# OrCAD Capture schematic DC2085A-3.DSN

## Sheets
1 PAGE1: size Custom; title: ADAPTOR BOARD; rev: 3; note: FAST TRACK 143A
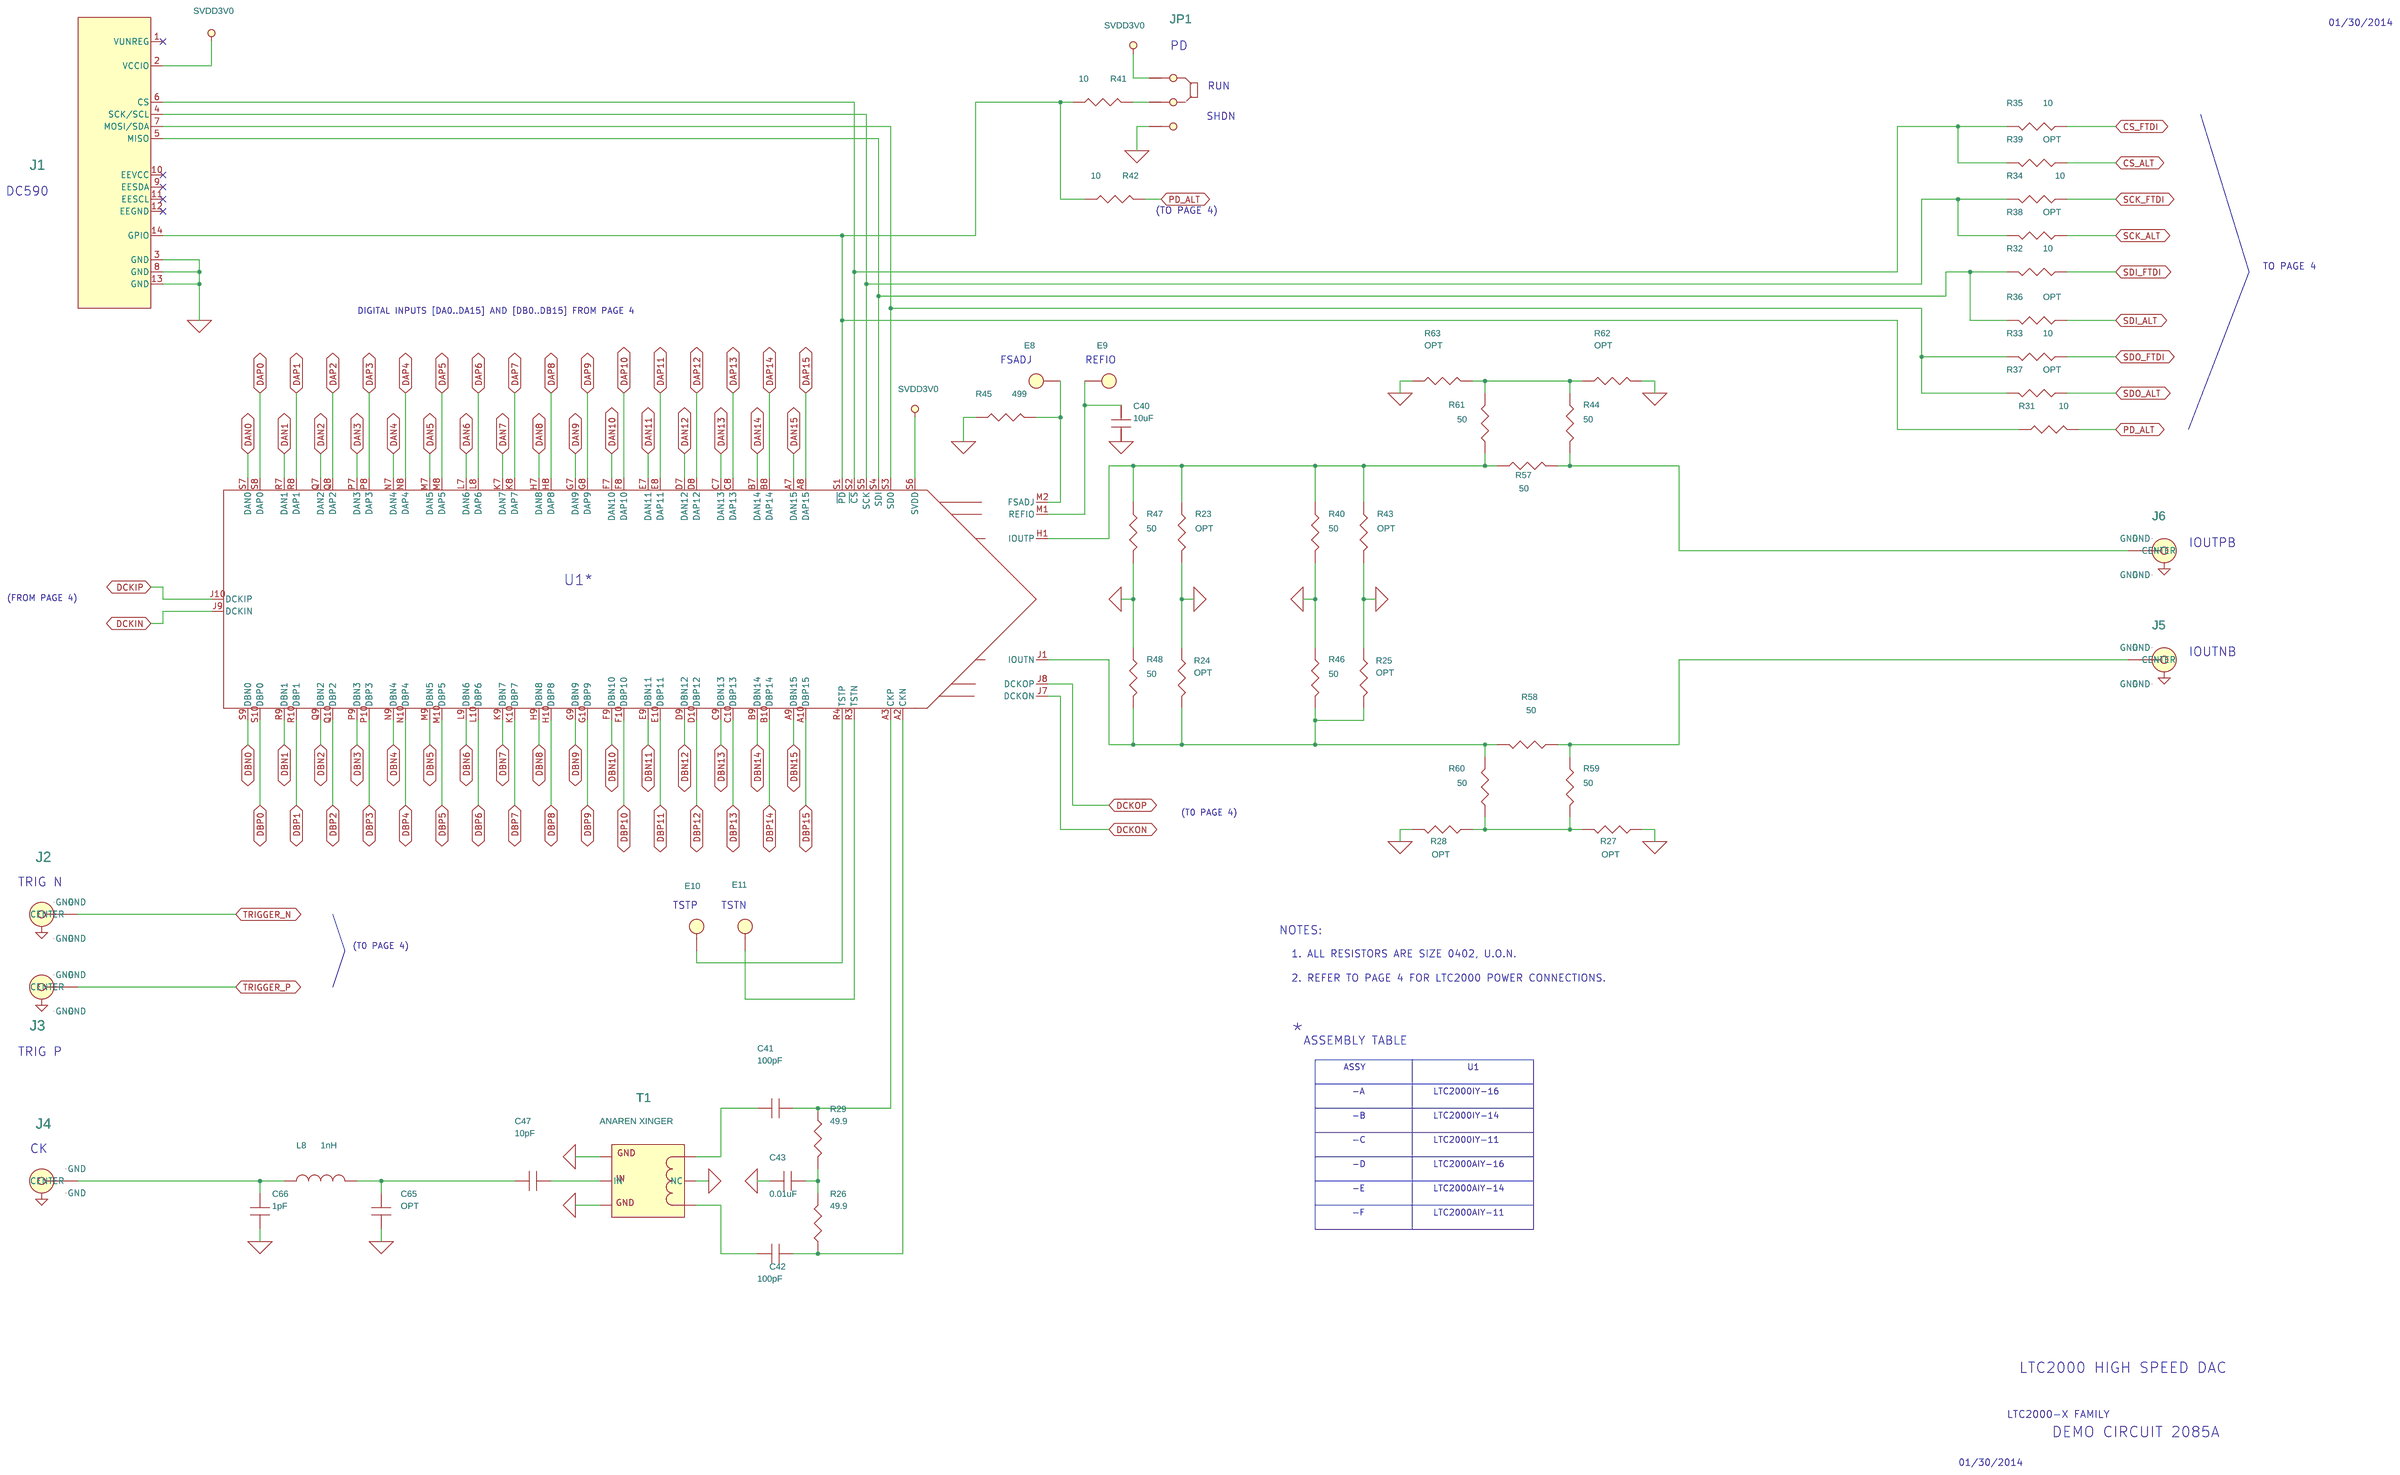
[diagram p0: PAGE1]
2 PAGE3: size Custom
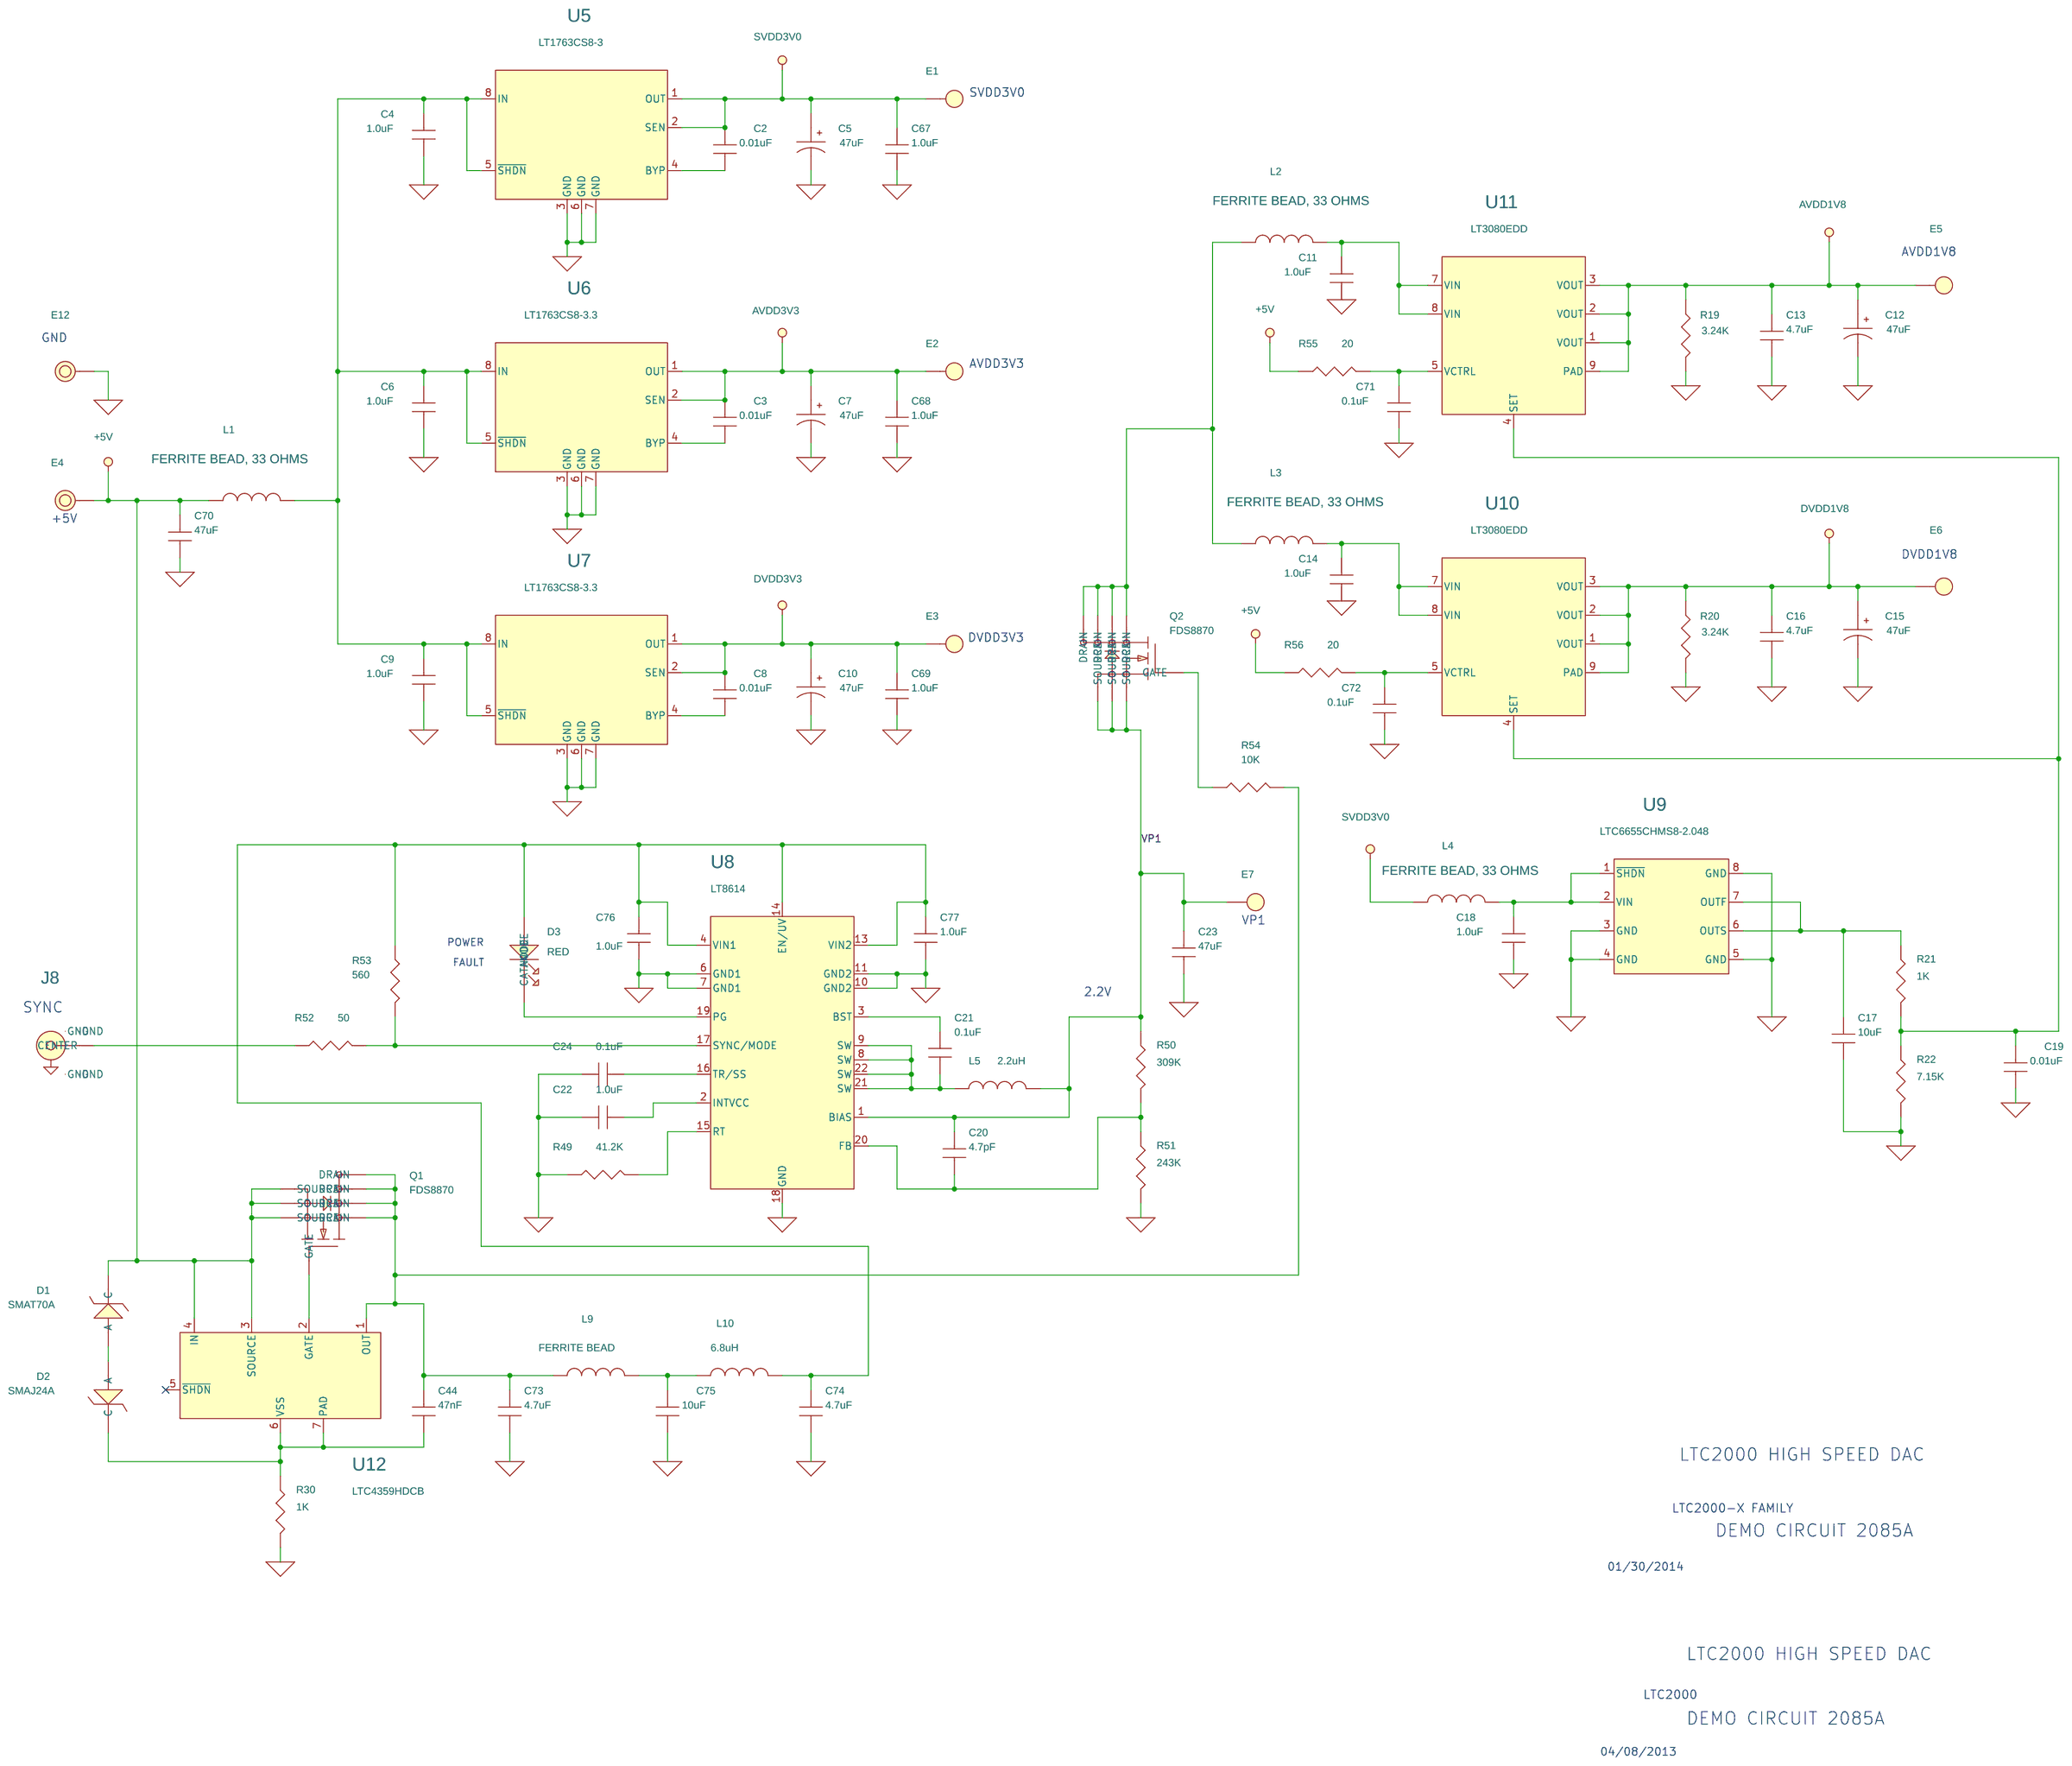
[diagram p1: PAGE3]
3 PAGE2: size Custom
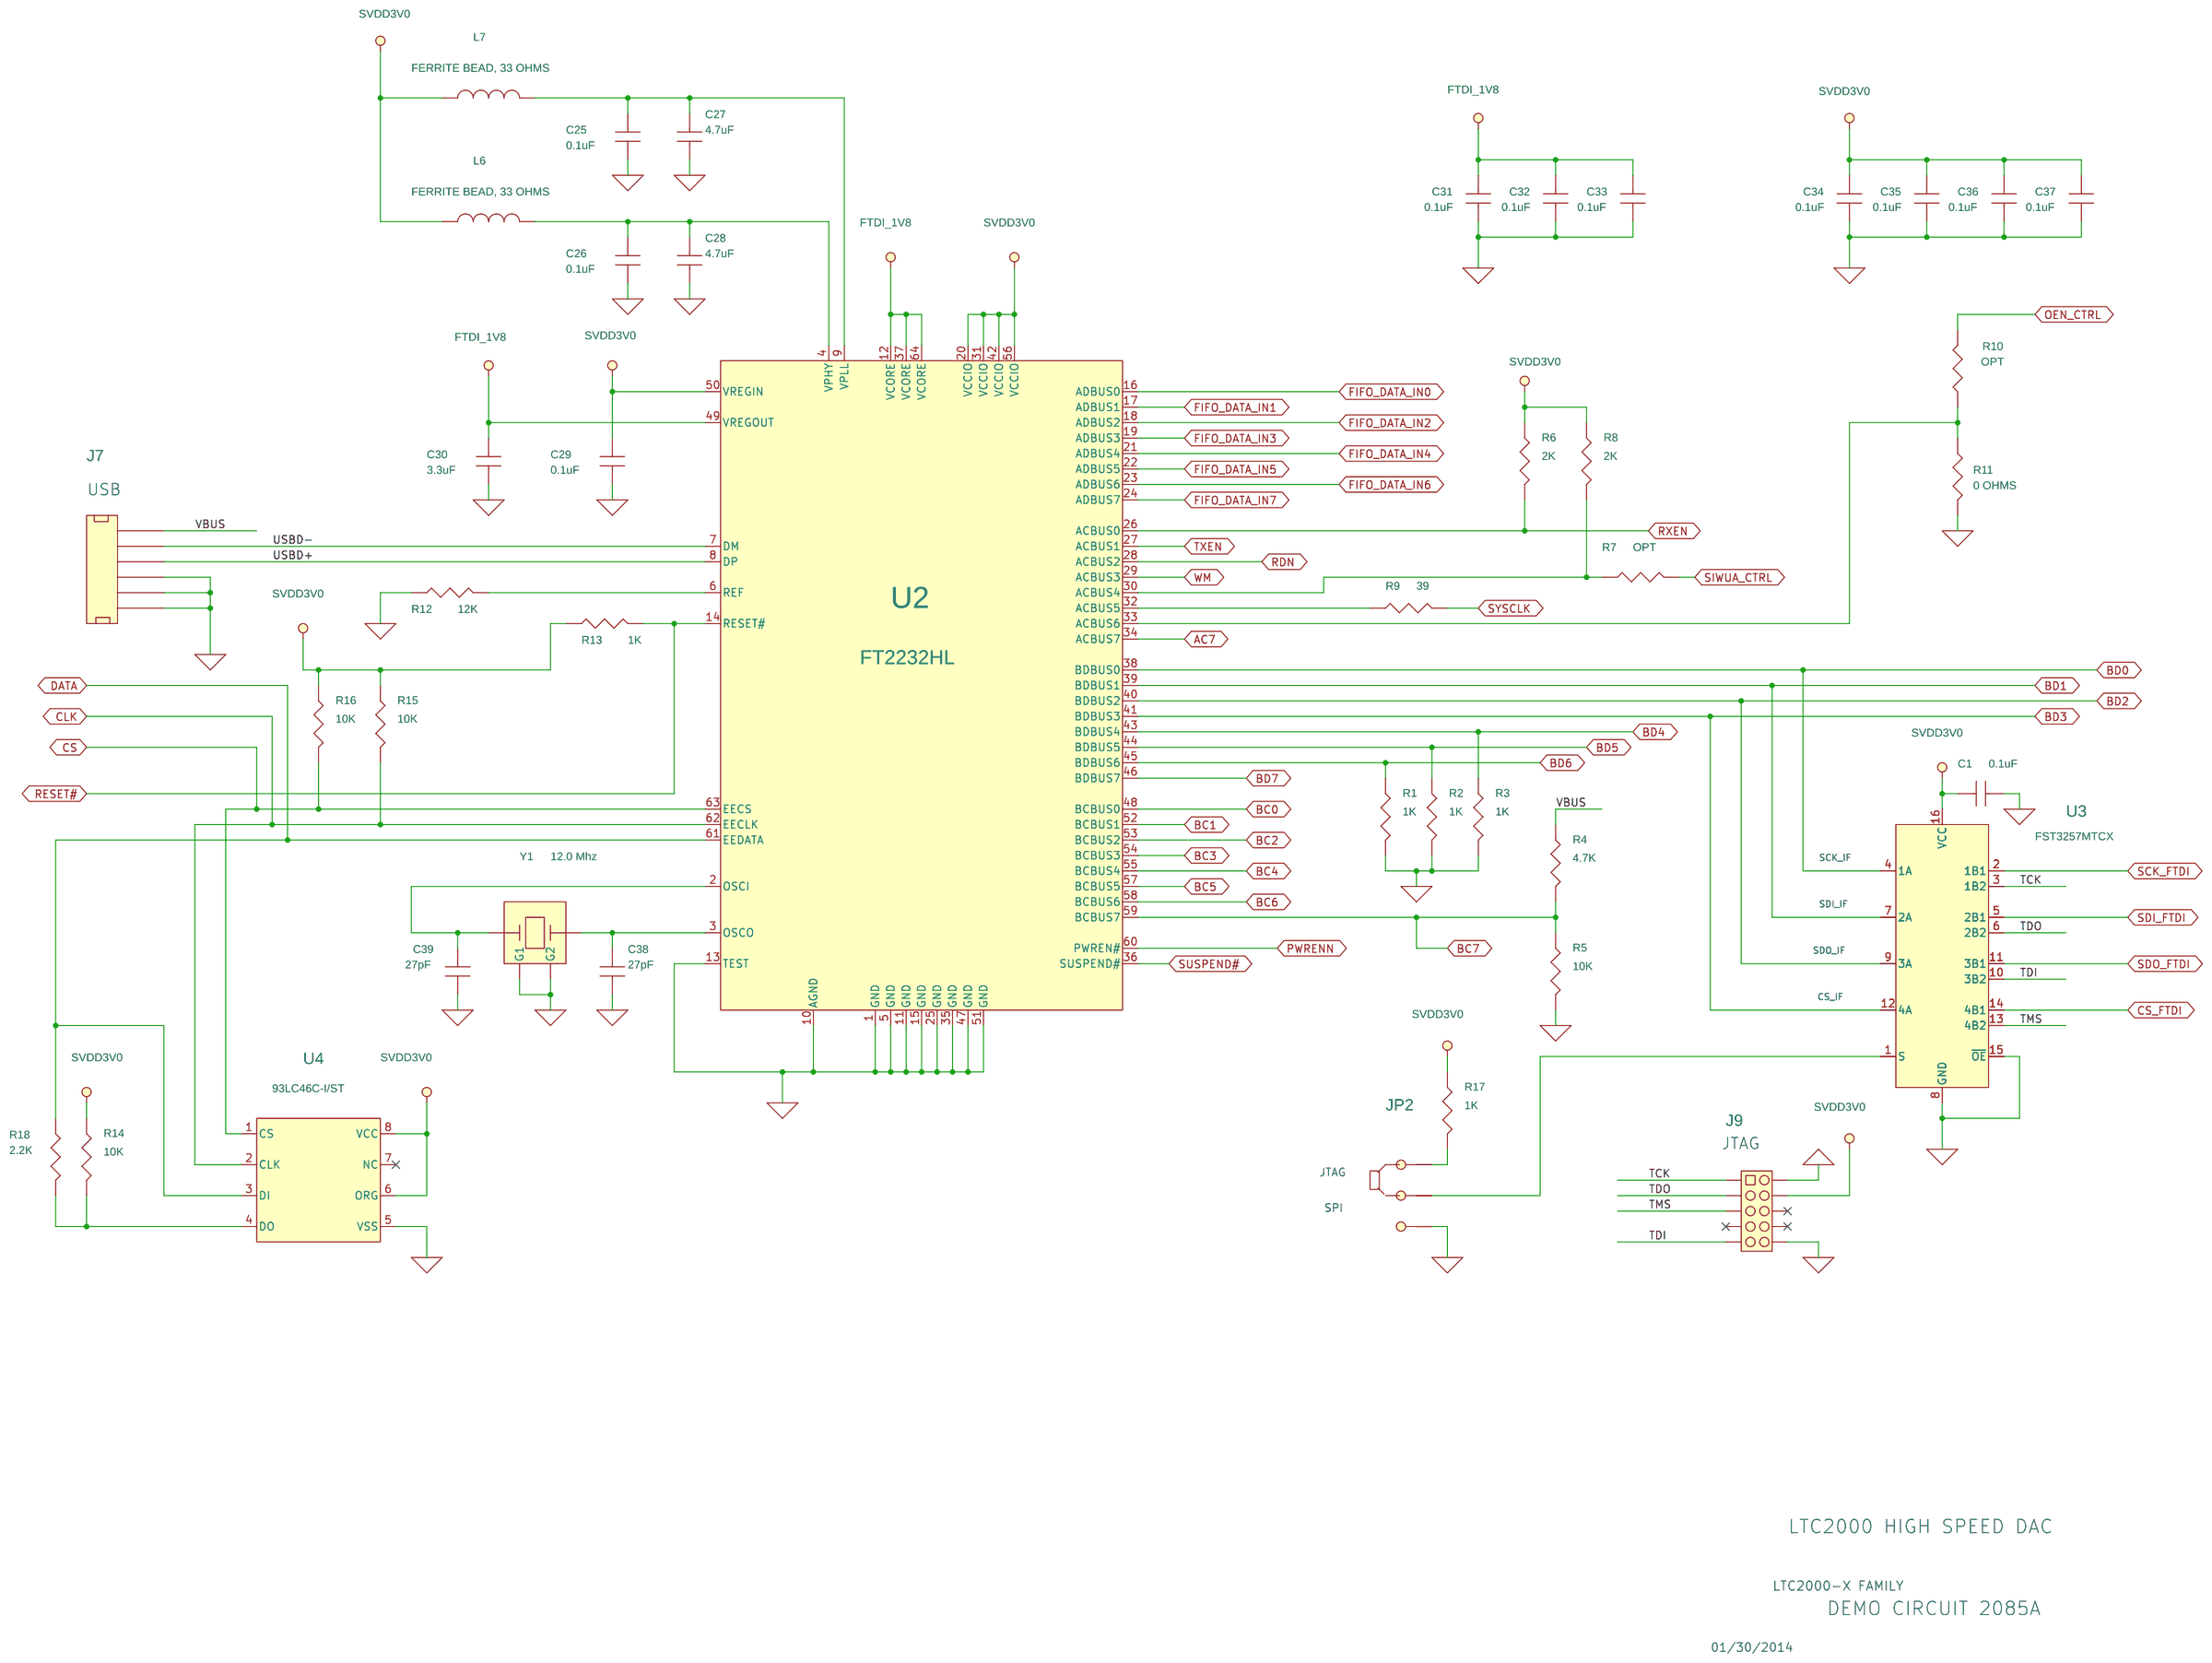
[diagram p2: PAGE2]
4 PAGE4: size Custom
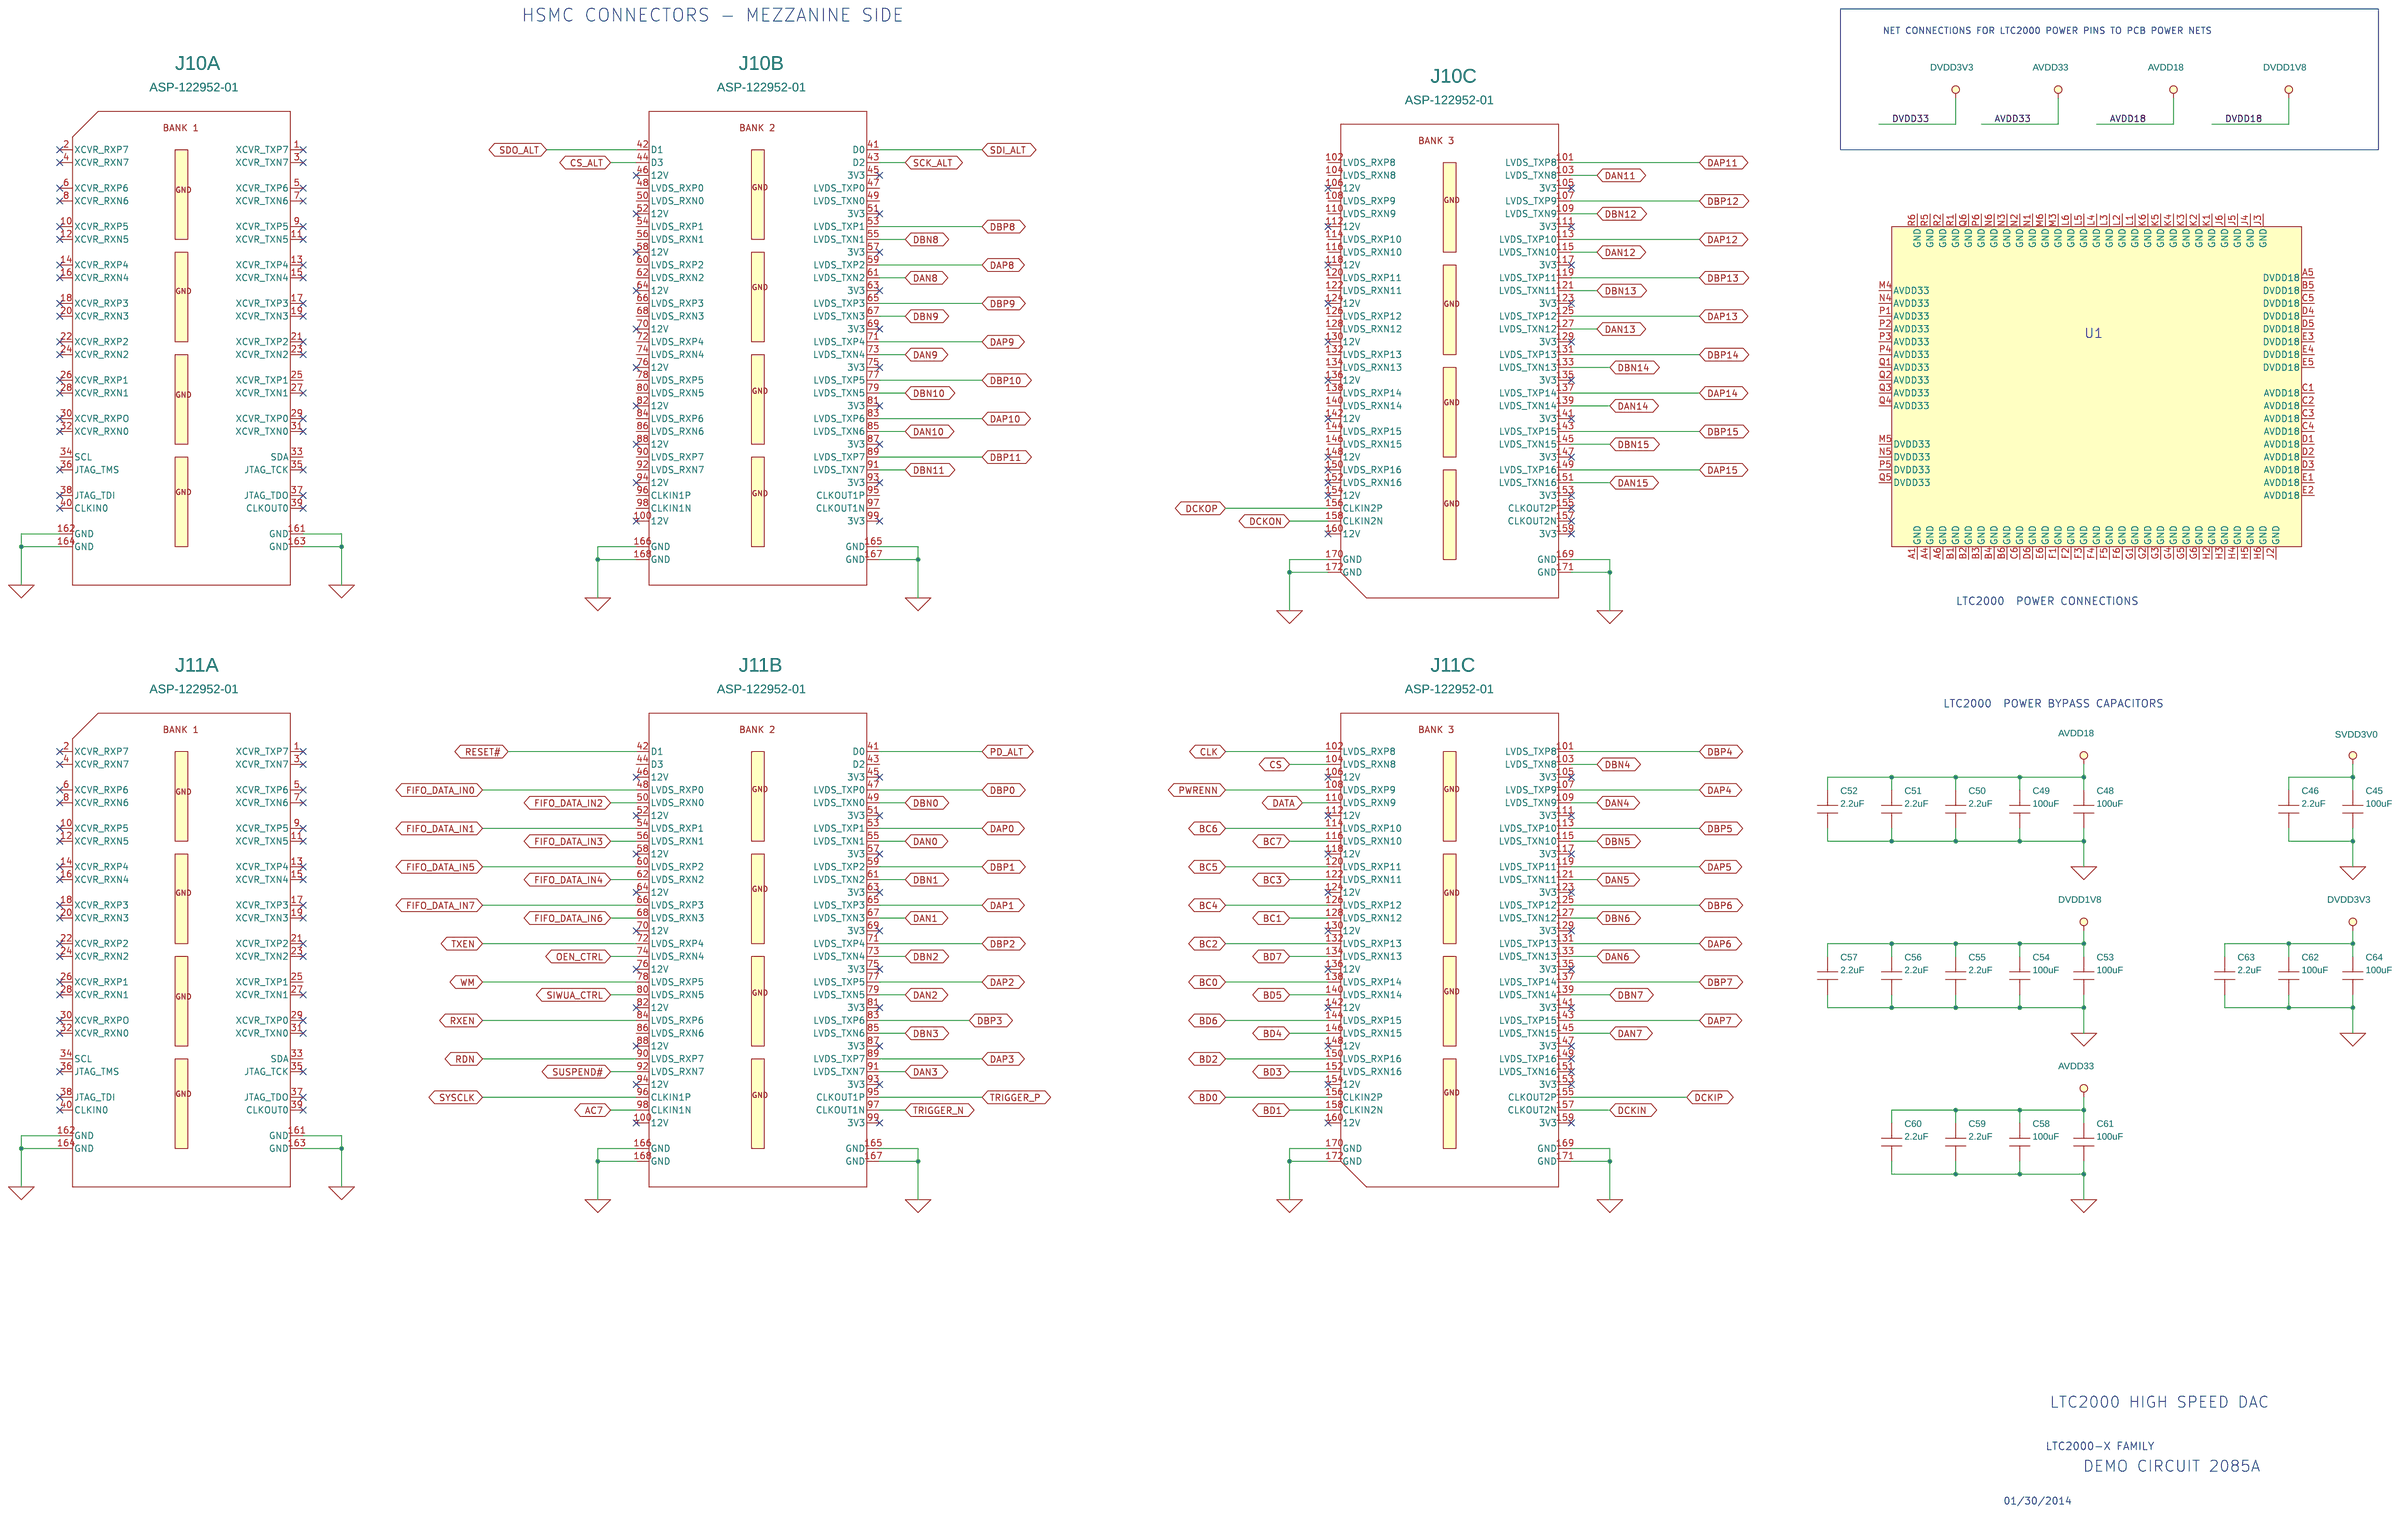
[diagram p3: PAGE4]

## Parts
sheet PAGE1
C40  10uF  [CC0603N]
C41  100pF  [CC0201L]
C42  100pF  [CC0201L]
C43  0.01uF  [CC0402N]
C47  10pF  [CC0201L]
C65  OPT  [CC0402L]
C66  1pF  [CC0402L]
E8  MILL-MAX 2308  [MILLMAX2308]
E9  MILL-MAX 2308  [MILLMAX2308]
E10  MILL-MAX 2308  [MILLMAX2308]
E11  MILL-MAX 2308  [MILLMAX2308]
J1  2X7 RIBBON CONN.  [HD2X7-079-MOLEX]
J2  SMA  [AMPHENOL-132134]
J3  SMA  [AMPHENOL-132134]
J4  SMA  [AEP9650-1113-005]
J5  SMA  [EFJOHNSON142-0701-851]
J6  SMA  [EFJOHNSON142-0701-851]
JP1  3 Pins 2mm Ctrs.  [JP3X1/079]
L8  1nH  [COILCRAFT-0402CS]
R23  OPT  [CR0402L]
R24  OPT  [CR0402L]
R25  OPT  [CR0402L]
R26  49.9  [CR0201L]
R27  OPT  [CR0402L]
R28  OPT  [CR0402L]
R29  49.9  [CR0201L]
R31  10  [CR0402N]
R32  10  [CR0402N]
R33  10  [CR0402N]
R34  10  [CR0402N]
R35  10  [CR0402N]
R36  OPT  [CR0402N]
R37  OPT  [CR0402N]
R38  OPT  [CR0402N]
R39  OPT  [CR0402N]
R40  50  [CR0402L]
R41  10  [CR0402N]
R42  10  [CR0402N]
R43  OPT  [CR0402L]
R44  50  [CR0402L]
R45  499  [CR0402N]
R46  50  [CR0402L]
R47  50  [CR0402L]
R48  50  [CR0402L]
R57  50  [CR0402L]
R58  50  [CR0402L]
R59  50  [CR0402L]
R60  50  [CR0402L]
R61  50  [CR0402L]
R62  OPT  [CR0402L]
R63  OPT  [CR0402L]
T1  ANAREN XINGER  [ANAREN-XINGER]
U1  LTC2000  [LTC-05-08-1890-REVB]  (sections A,B)
XJP2  2mm Ctrs.
sheet PAGE2
C1  0.1uF  [CC0402N]
C25  0.1uF  [CC0402N]
C26  0.1uF  [CC0402N]
C27  4.7uF  [CC1206N]
C28  4.7uF  [CC1206N]
C29  0.1uF  [CC0402N]
C30  3.3uF  [CC0603N]
C31  0.1uF  [CC0402N]
C32  0.1uF  [CC0402N]
C33  0.1uF  [CC0402N]
C34  0.1uF  [CC0402N]
C35  0.1uF  [CC0402N]
C36  0.1uF  [CC0402N]
C37  0.1uF  [CC0402N]
C38  27pF  [CC0402N]
C39  27pF  [CC0402N]
J7  USB RECEP TYPE B  [FCI-61729]
J9  HD2X5- .100  [SAMTEC_TSW-105-07-L-D]
JP2  3 Pins 2mm Ctrs.  [JP3X1/079]
L6  FERRITE BEAD, 33 OHMS  [IND1206N]
L7  FERRITE BEAD, 33 OHMS  [IND1206N]
R1  1K  [CR0402N]
R2  1K  [CR0402N]
R3  1K  [CR0402N]
R4  4.7K  [CR0402N]
R5  10K  [CR0402N]
R6  2K  [CR0402N]
R7  OPT  [CR0402N]
R8  2K  [CR0402N]
R9  39  [CR0402N]
R10  OPT  [CR0402N]
R11  0 OHMS  [CR0402N]
R12  12K  [CR0402N]
R13  1K  [CR0402N]
R14  10K  [CR0402N]
R15  10K  [CR0402N]
R16  10K  [CR0402N]
R17  1K  [CR0402N]
R18  2.2K  [CR0402N]
U2  FT2232HL  [FTDI-64LQFP]
U3  FST3257MTCX  [JEDEC-MO-153AB]
U4  93LC46C-I/ST  [MICROCHIP-TSSOP-8]
XJP1  2mm Ctrs.
Y1  12.0 Mhz  [ABRACON-ABMM2]
sheet PAGE3
C2  0.01uF  [CC0603N]
C3  0.01uF  [CC0603N]
C4  1.0uF  [CC0603N]
C5  47uF  [CAPTANT7343N]
C6  1.0uF  [CC0603N]
C7  47uF  [CAPTANT7343N]
C8  0.01uF  [CC0603N]
C9  1.0uF  [CC0603N]
C10  47uF  [CAPTANT7343N]
C11  1.0uF  [CC0603N]
C12  47uF  [CAPTANT7343N]
C13  4.7uF  [CC1206N]
C14  1.0uF  [CC0603N]
C15  47uF  [CAPTANT7343N]
C16  4.7uF  [CC1206N]
C17  10uF  [CC0603N]
C18  1.0uF  [CC0603N]
C19  0.01uF  [CC0603N]
C20  4.7pF  [CC0603N]
C21  0.1uF  [CC0603N]
C22  1.0uF  [CC0603N]
C23  47uF  [CC1210N]
C24  0.1uF  [CC0603N]
C44  47nF  [CC0402N]
C67  1.0uF  [CC0603N]
C68  1.0uF  [CC0603N]
C69  1.0uF  [CC0603N]
C70  47uF  [CC1210N]
C71  0.1uF  [CC0402N]
C72  0.1uF  [CC0402N]
C73  4.7uF  [CC1206N]
C74  4.7uF  [CC1206N]
C75  10uF  [CC1210N]
C76  1.0uF  [CC0603N]
C77  1.0uF  [CC0603N]
D1  SMAT70A  [DIODESINC-SMA]
D2  SMAJ24A  [DIODESINC-SMA]
D3  RED  [WURTH_LED_0805]
E1  MILL-MAX 2308  [MILLMAX2308]
E2  MILL-MAX 2308  [MILLMAX2308]
E3  MILL-MAX 2308  [MILLMAX2308]
E4  MILL MAX 2501  [MILLMAX2501]
E5  MILL-MAX 2308  [MILLMAX2308]
E6  MILL-MAX 2308  [MILLMAX2308]
E7  MILL-MAX 2308  [MILLMAX2308]
E12  MILL MAX 2501  [MILLMAX2501]
J8  SMA  [AMPHENOL-132134]
L1  FERRITE BEAD, 33 OHMS  [IND1206N]
L2  FERRITE BEAD, 33 OHMS  [IND1206N]
L3  FERRITE BEAD, 33 OHMS  [IND1206N]
L4  FERRITE BEAD, 33 OHMS  [IND1206N]
L5  2.2uH  [VISHAY-IHLP-2020BZ-11]
L9  FERRITE BEAD  [IND_MPZ2012]
L10  6.8uH  [VISHAY-IHLP-2020CZ-01]
Q1  FDS8870  [SOIC-8]
Q2  FDS8870  [SOIC-8]
R19  3.24K  [CR0402N]
R20  3.24K  [CR0402N]
R21  1K  [CR0402N]
R22  7.15K  [CR0402N]
R30  1K  [CR0402N]
R49  41.2K  [CR0603N]
R50  309K  [CR0603N]
R51  243K  [CR0603N]
R52  50  [CR0603N]
R53  560  [CR0603N]
R54  10K  [CR0603N]
R55  20  [CR0402N]
R56  20  [CR0402N]
U5  LT1763CS8-3  [LTC-S8]
U6  LT1763CS8-3.3  [LTC-S8]
U7  LT1763CS8-3.3  [LTC-S8]
U8  LT8614  [LTC-UDC-AA]
U9  LTC6655CHMS8-2.048  [LTC-MS8]
U10  LT3080EDD  [LTC-DD8]
U11  LT3080EDD  [LTC-DD8]
U12  LTC4359HDCB  [LTC-DCB6]
sheet PAGE4
C45  100uF  [CC1206N]
C46  2.2uF  [CC0306L]
C48  100uF  [CC1206N]
C49  100uF  [CC1206N]
C50  2.2uF  [CC0306L]
C51  2.2uF  [CC0306L]
C52  2.2uF  [CC0306L]
C53  100uF  [CC1206N]
C54  100uF  [CC1206N]
C55  2.2uF  [CC0306L]
C56  2.2uF  [CC0306L]
C57  2.2uF  [CC0306L]
C58  100uF  [CC1206N]
C59  2.2uF  [CC0306L]
C60  2.2uF  [CC0306L]
C61  100uF  [CC1206N]
C62  100uF  [CC1206N]
C63  2.2uF  [CC0306L]
C64  100uF  [CC1206N]
J10  ASP-122952-01  [CON-SAMTEC-ASP-122952-01]  (sections A,B,C)
J11  ASP-122952-01  [CON-SAMTEC-ASP-122952-01]  (sections A,B,C)

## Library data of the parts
C17 C40 = 10uF_10V_20%_X5R_0603
C41 C42 = 100pF_25V_5%_COG_0201
C43 = 0.01uF_16V_10%_X5R_0402
C47 = 10pF_25V_5%_COG_0201
C65 = OPT_0402
C66 = 1pF_25V_+_-.25pF_NP0_0402
E1-E3 E5-E11 = TEST_POINT,_.156,_MILL-MAX_2308
J1 = CONN,_2X7_.079_MOLEX_RIBBON
J2 J3 J8 = CON.,_SMA,_50_OHM_STRAIGHT
J4 = CON.,_SMA_,_SMT,_AEP-9650
J5 J6 = CON.,_SMA,_50_OHM_EDGE-LAUNCH
JP1 JP2 = 3_PIN_HEADER_B_.079_SINGLE_ROW
L8 = IND.,1nH,_COILCRAFT_0402CS
R7 R10 R23-R25 R27 R28 R36-R39 R43 R62 R63 = OPT_0402_v2
R26 R29 = 49.9_OHMS_1%_1_16W_0201
R31-R35 R41 R42 = 10_OHMS_5%_1_10W_0402
R40 R44 R46-R48 R57-R61 = 50_OHMS_0.1%_1_20W_0402_HI_FQ
R45 = 499_1%_1_16W_0402
T1 = BALUN,_B0430J50100A00
U1 = LTC2000: Part Number: LINEAR TECH., LTC2000IYBGA
XJP1 XJP2 = SHUNT,_2MM
C1 C25 C26 C29 C31-C37 C71 C72 = 0.1uF_16V_10%_X7R_0402
C13 C16 C27 C28 = 4.7uF_16V_20%_X5R_1206
C30 = 3.3uF_16V_10%_X5R_0603
C38 C39 = 27pF_50V_5%_NPO_0402
J7 = USB_TYPE_B_RECEPT_61729
J9 = CONN.,_JTAG,_2X5,_0.100
L1-L4 L6 L7 = FERRITE_BEAD,_33_OHM,_1206
R1-R3 R13 R17 R30 = 1K_5%_1_16W_0402
R4 = 4.7K_5%_1_16W_0402
R5 R14-R16 = 10K_5%_1_16W_0402
R6 R8 = 2K_5%_1_16W_0402
R9 = 39_OHMS_1%_1_16W_0402
R11 = 0.0_OHMS_1_16W_0402
R12 = 12K_5%_1_16W_0402
R18 = 2.2K_5%_1_16W_0402
U2 = FT2232H
U3 = FST3257MTCX_16TSSOP
U4 = 93LC46C-I_ST_TSSOP: IC, EEPROM 1KBIT 3MHZ, TSSOP-8
Y1 = XTAL_12MHZ_ABMM2
C2 C3 C8 C19 = 0.01uF_25V_5%_NPO_0603
C4 C6 C9 C11 C14 C18 C67-C69 = 1.0uF_16V_10%_X7R_0603
C5 C7 C10 C12 C15 = 47uF_16V_10%_TANT._7343
C20 = 4.7pF_50V_+_-_0.25pF_C0G_0603
C21 C24 = 0.1uF_16V_10%_X7R_0603
C22 = 1.0uF_25V_10%_X7R_0603
C23 C70 = 47uF_10V_10%_X7R_1210
C44 = 47nF_25V_10%_X7R_0402
C73 C74 = 4.7uF_50V_10%_X7R_1206
C75 = 10uF_50V_10%_X7R_1210
C76 C77 = 1.0uF_50V_10%_X5R_0603
D1 = DIODE,_TVS,_SMAT70A,_SMA
D2 = DIODE,_TVS,_SMAJ24A,_SMA
D3 = LED,RED,_0805,_WURTH
E4 E12 = TESTPOINT,_.219,_MILL-_MAX_2501
L5 = IND.,_2.2uH,_VISHAY_IHLP
L9 = FERRITE_BEAD,_30_OHM,_0805
L10 = IND.,_6.8uH,_VISHAY_IHLP
Q1 Q2 = FDS8870,_FAIRCHILD
R19 R20 = 3.24K_1%_1_10W_0402
R21 = 1K_1%_1_16W_0402
R22 = 7.15K_1%_1_16W_0402
R49 = 41.2K_1%_1_10W_0603
R50 = 309K_1%_1_10W_0603
R51 = 243K_1%_1_10W_0603
R52 = 50_OHMS_5%_1_8W_0603
R53 = 560_OHMS_5%_1_10W_0603
R54 = 10K_1%_1_10W_0603
R55 R56 = 20_OHMS_1%_1_16W_0402
U5 = LT1763CS8-3
U6 U7 = LT1763CS8-3.3
U8 = LT8614
U9 = LTC6655-2.048
U10 U11 = LT3080EDD
U12 = LTC4359HDCB
C45 C48 C49 C53 C54 C58 C61 C62 C64 = 100uF_6.3V_20%_X5R_1206
C46 C50-C52 C55-C57 C59 C60 C63 = 2.2uF_4V_20%_X7S_0306
J10 J11 = HSMC_CONNECTOR,_ASP-122952-01_4

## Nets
+5V: C70.1 D1.1(C) E4.1 L1.1 Q1.1(SOURCE) Q1.2(SOURCE) Q1.3(SOURCE) R55.1 R56.1 U12.3(SOURCE) U12.4(IN)
AVDD1V8: C12.1 C13.1 C48.1 C49.1 C50.1 C51.1 C52.1 E5.1(A) R19.1 U1.C1(AVDD18) U1.C2(AVDD18) U1.C3(AVDD18) U1.C4(AVDD18) U1.D1(AVDD18) U1.D2(AVDD18) U1.D3(AVDD18) U1.E1(AVDD18) U1.E2(AVDD18) U11.1(VOUT) U11.2(VOUT) U11.3(VOUT) U11.9(PAD)
AVDD3V3: C3.1 C7.1 C58.1 C59.1 C60.1 C61.1 C68.1 E2.1(A) U1.M4(AVDD33) U1.N4(AVDD33) U1.P1(AVDD33) U1.P2(AVDD33) U1.P3(AVDD33) U1.P4(AVDD33) U1.Q1(AVDD33) U1.Q2(AVDD33) U1.Q3(AVDD33) U1.Q4(AVDD33) U6.1(OUT) U6.2(SEN)
DVDD1V8: C15.1 C16.1 C53.1 C54.1 C55.1 C56.1 C57.1 E6.1(A) R20.1 U1.A5(DVDD18) U1.B5(DVDD18) U1.C5(DVDD18) U1.D4(DVDD18) U1.D5(DVDD18) U1.E3(DVDD18) U1.E4(DVDD18) U1.E5(DVDD18) U10.1(VOUT) U10.2(VOUT) U10.3(VOUT) U10.9(PAD)
DVDD33: C8.1 C10.1 C62.1 C63.1 C64.1 C69.1 E3.1(A) U1.M5(DVDD33) U1.N5(DVDD33) U1.P5(DVDD33) U1.Q5(DVDD33) U7.1(OUT) U7.2(SEN)
GND: C1.2 C4.2 C5.2 C6.2 C7.2 C9.2 C10.2 C11.2 C12.2 C13.2 C14.2 C15.2 C16.2 C17.2 C18.2 C19.2 C22.1 C23.2 C24.1 C25.1 C26.1 C27.2 C28.2 C29.1 C30.2 C31.1 C32.1 C33.1 C34.1 C35.1 C36.1 C37.1 C38.2 C39.2 C40.2 C43.1 C45.2 C46.2 C48.2 C49.2 C50.2 C51.2 C52.2 C53.2 C54.2 C55.2 C56.2 C57.2 C58.2 C59.2 C60.2 C61.2 C62.2 C63.2 C64.2 C65.2 C66.2 C67.2 C68.2 C69.2 C70.2 C71.1 C72.1 C73.2 C74.2 C75.2 C76.2 C77.2 E12.1 J1.3(GND) J1.8(GND) J1.13(GND) J2.2(GND) J2.3(GND) J2.4(GND) J2.5(GND) J3.2(GND) J3.3(GND) J3.4(GND) J3.5(GND) J4.2(GND) J4.3(GND) J5.2(GND) J5.3(GND) J5.4(GND) J5.5(GND) J6.2(GND) J6.3(GND) J6.4(GND) J6.5(GND) J7.4 J7.5 J7.6 J8.2(GND) J8.3(GND) J8.4(GND) J8.5(GND) J9.2 J9.10 J10.161(GND) J10.162(GND) J10.163(GND) J10.164(GND) J10.165(GND) J10.166(GND) J10.167(GND) J10.168(GND) J10.169(GND) J10.170(GND) J10.171(GND) J10.172(GND) J11.161(GND) J11.162(GND) J11.163(GND) J11.164(GND) J11.165(GND) J11.166(GND) J11.167(GND) J11.168(GND) J11.169(GND) J11.170(GND) J11.171(GND) J11.172(GND) JP1.3 JP2.3 R1.2 R2.2 R3.2 R5.2 R11.2 R12.1 R19.2 R20.2 R22.2 R23.2 R24.2 R25.2 R27.1 R28.2 R30.2 R40.2 R43.2 R45.1 R46.1 R47.2 R48.1 R49.1 R51.2 R62.1 R63.2 T1.1 T1.3 T1.5(NC) U1.A1(GND) U1.A4(GND) U1.A6(GND) U1.B1(GND) U1.B2(GND) U1.B3(GND) U1.B4(GND) U1.B6(GND) U1.C6(GND) U1.D6(GND) U1.E6(GND) U1.F1(GND) U1.F2(GND) U1.F3(GND) U1.F4(GND) U1.F5(GND) U1.F6(GND) U1.G1(GND) U1.G2(GND) U1.G3(GND) U1.G4(GND) U1.G5(GND) U1.G6(GND) U1.H2(GND) U1.H3(GND) U1.H4(GND) U1.H5(GND) U1.H6(GND) U1.J2(GND) U1.J3(GND) U1.J4(GND) U1.J5(GND) U1.J6(GND) U1.K1(GND) U1.K2(GND) U1.K3(GND) U1.K4(GND) U1.K5(GND) U1.K6(GND) U1.L1(GND) U1.L2(GND) U1.L3(GND) U1.L4(GND) U1.L5(GND) U1.L6(GND) U1.M3(GND) U1.M6(GND) U1.N1(GND) U1.N2(GND) U1.N3(GND) U1.N6(GND) U1.P6(GND) U1.Q6(GND) U1.R1(GND) U1.R2(GND) U1.R5(GND) U1.R6(GND) U2.1(GND) U2.5(GND) U2.10(AGND) U2.11(GND) U2.13(TEST) U2.15(GND) U2.25(GND) U2.35(GND) U2.47(GND) U2.51(GND) U3.8(GND) U3.15(~{OE}) U4.5(VSS) U5.3(GND) U5.6(GND) U5.7(GND) U6.3(GND) U6.6(GND) U6.7(GND) U7.3(GND) U7.6(GND) U7.7(GND) U8.6(GND1) U8.7(GND1) U8.10(GND2) U8.11(GND2) U8.18(GND) U9.3(GND) U9.4(GND) U9.5(GND) U9.8(GND) Y1.2(G1) Y1.4(G2)
SVDD3V0: C1.1 C2.1 C5.1 C29.2 C34.2 C35.2 C36.2 C37.2 C45.1 C46.1 C67.1 E1.1(A) J1.2(VCCIO) J9.4 JP1.1 L4.1 L6.1 L7.1 R6.1 R8.1 R13.1 R14.1 R15.1 R16.1 R17.1 U1.S6(SVDD) U2.20(VCCIO) U2.31(VCCIO) U2.42(VCCIO) U2.50(VREGIN) U2.56(VCCIO) U3.16(VCC) U4.6(ORG) U4.8(VCC) U5.1(OUT) U5.2(SEN)
VBUS: J7.1 R4.1
AC7: J11.98(CLKIN1N) U2.34(ACBUS7)
BC0: J11.138(LVDS_RXP14) U2.48(BCBUS0)
BC1: J11.128(LVDS_RXN12) U2.52(BCBUS1)
BC2: J11.132(LVDS_RXP13) U2.53(BCBUS2)
BC3: J11.122(LVDS_RXN11) U2.54(BCBUS3)
BC4: J11.126(LVDS_RXP12) U2.55(BCBUS4)
BC5: J11.120(LVDS_RXP11) U2.57(BCBUS5)
BC6: J11.114(LVDS_RXP10) U2.58(BCBUS6)
BC7: J11.116(LVDS_RXN10) R4.2 R5.1 U2.59(BCBUS7)
BD0: J11.156(CLKIN2P) U2.38(BDBUS0) U3.4(1A)
BD1: J11.158(CLKIN2N) U2.39(BDBUS1) U3.7(2A)
BD2: J11.150(LVDS_RXP16) U2.40(BDBUS2) U3.9(3A)
BD3: J11.152(LVDS_RXN16) U2.41(BDBUS3) U3.12(4A)
BD4: J11.146(LVDS_RXN15) R3.1 U2.43(BDBUS4)
BD5: J11.140(LVDS_RXN14) R2.1 U2.44(BDBUS5)
BD6: J11.144(LVDS_RXP15) R1.1 U2.45(BDBUS6)
BD7: J11.134(LVDS_RXN13) U2.46(BDBUS7)
CLK: J11.102(LVDS_RXP8) R15.2 U2.62(EECLK) U4.2(CLK)
CS: J11.104(LVDS_RXN8) R16.2 U2.63(EECS) U4.1(CS)
CS_ALT: J10.44(D3) R39.2
CS_FTDI: R35.2 U3.14(4B1)
DAN0: J11.55(LVDS_TXN1) U1.S7(DAN0)
DAN1: J11.67(LVDS_TXN3) U1.R7(DAN1)
DAN2: J11.79(LVDS_TXN5) U1.Q7(DAN2)
DAN3: J11.91(LVDS_TXN7) U1.P7(DAN3)
DAN4: J11.109(LVDS_TXN9) U1.N7(DAN4)
DAN5: J11.121(LVDS_TXN11) U1.M7(DAN5)
DAN6: J11.133(LVDS_TXN13) U1.L7(DAN6)
DAN7: J11.145(LVDS_TXN15) U1.K7(DAN7)
DAN8: J10.61(LVDS_TXN2) U1.H7(DAN8)
DAN9: J10.73(LVDS_TXN4) U1.G7(DAN9)
DAN10: J10.85(LVDS_TXN6) U1.F7(DAN10)
DAN11: J10.103(LVDS_TXN8) U1.E7(DAN11)
DAN12: J10.115(LVDS_TXN10) U1.D7(DAN12)
DAN13: J10.127(LVDS_TXN12) U1.C7(DAN13)
DAN14: J10.139(LVDS_TXN14) U1.B7(DAN14)
DAN15: J10.151(LVDS_TXN16) U1.A7(DAN15)
DAP0: J11.53(LVDS_TXP1) U1.S8(DAP0)
DAP1: J11.65(LVDS_TXP3) U1.R8(DAP1)
DAP2: J11.77(LVDS_TXP5) U1.Q8(DAP2)
DAP3: J11.89(LVDS_TXP7) U1.P8(DAP3)
DAP4: J11.107(LVDS_TXP9) U1.N8(DAP4)
DAP5: J11.119(LVDS_TXP11) U1.M8(DAP5)
DAP6: J11.131(LVDS_TXP13) U1.L8(DAP6)
DAP7: J11.143(LVDS_TXP15) U1.K8(DAP7)
DAP8: J10.59(LVDS_TXP2) U1.H8(DAP8)
DAP9: J10.71(LVDS_TXP4) U1.G8(DAP9)
DAP10: J10.83(LVDS_TXP6) U1.F8(DAP10)
DAP11: J10.101(LVDS_TXP8) U1.E8(DAP11)
DAP12: J10.113(LVDS_TXP10) U1.D8(DAP12)
DAP13: J10.125(LVDS_TXP12) U1.C8(DAP13)
DAP14: J10.137(LVDS_TXP14) U1.B8(DAP14)
DAP15: J10.149(LVDS_TXP16) U1.A8(DAP15)
DATA: J11.110(LVDS_RXN9) R18.1 U2.61(EEDATA) U4.3(DI)
DBN0: J11.49(LVDS_TXN0) U1.S9(DBN0)
DBN1: J11.61(LVDS_TXN2) U1.R9(DBN1)
DBN2: J11.73(LVDS_TXN4) U1.Q9(DBN2)
DBN3: J11.85(LVDS_TXN6) U1.P9(DBN3)
DBN4: J11.103(LVDS_TXN8) U1.N9(DBN4)
DBN5: J11.115(LVDS_TXN10) U1.M9(DBN5)
DBN6: J11.127(LVDS_TXN12) U1.L9(DBN6)
DBN7: J11.139(LVDS_TXN14) U1.K9(DBN7)
DBN8: J10.55(LVDS_TXN1) U1.H9(DBN8)
DBN9: J10.67(LVDS_TXN3) U1.G9(DBN9)
DBN10: J10.79(LVDS_TXN5) U1.F9(DBN10)
DBN11: J10.91(LVDS_TXN7) U1.E9(DBN11)
DBN12: J10.109(LVDS_TXN9) U1.D9(DBN12)
DBN13: J10.121(LVDS_TXN11) U1.C9(DBN13)
DBN14: J10.133(LVDS_TXN13) U1.B9(DBN14)
DBN15: J10.145(LVDS_TXN15) U1.A9(DBN15)
DBP0: J11.47(LVDS_TXP0) U1.S10(DBP0)
DBP1: J11.59(LVDS_TXP2) U1.R10(DBP1)
DBP2: J11.71(LVDS_TXP4) U1.Q10(DBP2)
DBP3: J11.83(LVDS_TXP6) U1.P10(DBP3)
DBP4: J11.101(LVDS_TXP8) U1.N10(DBP4)
DBP5: J11.113(LVDS_TXP10) U1.M10(DBP5)
DBP6: J11.125(LVDS_TXP12) U1.L10(DBP6)
DBP7: J11.137(LVDS_TXP14) U1.K10(DBP7)
DBP8: J10.53(LVDS_TXP1) U1.H10(DBP8)
DBP9: J10.65(LVDS_TXP3) U1.G10(DBP9)
DBP10: J10.77(LVDS_TXP5) U1.F10(DBP10)
DBP11: J10.89(LVDS_TXP7) U1.E10(DBP11)
DBP12: J10.107(LVDS_TXP9) U1.D10(DBP12)
DBP13: J10.119(LVDS_TXP11) U1.C10(DBP13)
DBP14: J10.131(LVDS_TXP13) U1.B10(DBP14)
DBP15: J10.143(LVDS_TXP15) U1.A10(DBP15)
DCKIN: J11.157(CLKOUT2N) U1.J9(DCKIN)
DCKIP: J11.155(CLKOUT2P) U1.J10(DCKIP)
DCKON: J10.158(CLKIN2N) U1.J7(DCKON)
DCKOP: J10.156(CLKIN2P) U1.J8(DCKOP)
FIFO_DATA_IN0: J11.48(LVDS_RXP0) U2.16(ADBUS0)
FIFO_DATA_IN1: J11.54(LVDS_RXP1) U2.17(ADBUS1)
FIFO_DATA_IN2: J11.50(LVDS_RXN0) U2.18(ADBUS2)
FIFO_DATA_IN3: J11.56(LVDS_RXN1) U2.19(ADBUS3)
FIFO_DATA_IN4: J11.62(LVDS_RXN2) U2.21(ADBUS4)
FIFO_DATA_IN5: J11.60(LVDS_RXP2) U2.22(ADBUS5)
FIFO_DATA_IN6: J11.68(LVDS_RXN3) U2.23(ADBUS6)
FIFO_DATA_IN7: J11.66(LVDS_RXP3) U2.24(ADBUS7)
FTDI_1V8: C30.1 C31.2 C32.2 C33.2 U2.12(VCORE) U2.37(VCORE) U2.49(VREGOUT) U2.64(VCORE)
OEN_CTRL: J11.74(LVDS_RXN4) R10.2
PD_ALT: J11.41(D0) R31.2 R42.1
PWRENN: J11.108(LVDS_RXP9) U2.60(PWREN#)
RDN: J11.90(LVDS_RXP7) U2.28(ACBUS2)
RESET#: J11.42(D1) R13.2 U2.14(RESET#)
RXEN: J11.84(LVDS_RXP6) R6.2 U2.26(ACBUS0)
SCK_ALT: J10.43(D2) R38.2
SCK_FTDI: R34.2 U3.2(1B1)
SDI_ALT: J10.41(D0) R36.2
SDI_FTDI: R32.2 U3.5(2B1)
SDO_ALT: J10.42(D1) R37.2
SDO_FTDI: R33.2 U3.11(3B1)
SIWUA_CTRL: J11.80(LVDS_RXN5) R7.2
SUSPEND#: J11.92(LVDS_RXN7) U2.36(SUSPEND#)
SYSCLK: J11.96(CLKIN1P) R9.2
TCK: J9.1 U3.3(1B2)
TDI: J9.9 U3.10(3B2)
TDO: J9.3 U3.6(2B2)
TMS: J9.5 U3.13(4B2)
TRIGGER_N: J2.1(CENTER) J11.97(CLKOUT1N)
TRIGGER_P: J3.1(CENTER) J11.95(CLKOUT1P)
TXEN: J11.72(LVDS_RXP4) U2.27(ACBUS1)
USBD+: J7.3 U2.8(DP)
USBD-: J7.2 U2.7(DM)
VP1: C20.1 C23.1 E7.1(A) L5.2 Q2.1(SOURCE) Q2.2(SOURCE) Q2.3(SOURCE) R50.1 U8.1(BIAS)
WM: J11.78(LVDS_RXP5) U2.29(ACBUS3)
N17112334: R7.1 R8.2 U2.30(ACBUS4)
N17118183: R9.1 U2.32(ACBUS5)
N17119796: R10.1 R11.1 U2.33(ACBUS6)
N17130639: R12.2 U2.6(REF)
N17160387: JP2.2 U3.1(S)
N17163559: JP2.1 R17.2
N17181216: R14.2 R18.2 U4.4(DO)
N17192608: C2.2 U5.4(BYP)
N17194743: C4.1 C6.1 C9.1 L1.2 U5.5(~{SHDN}) U5.8(IN) U6.5(~{SHDN}) U6.8(IN) U7.5(~{SHDN}) U7.8(IN)
N17200213: C3.2 U6.4(BYP)
N17200607: C8.2 U7.4(BYP)
N17221258: C11.1 L2.2 U11.7(VIN) U11.8(VIN)
N17230681: C14.1 L3.2 U10.7(VIN) U10.8(VIN)
N17236206: C19.1 R21.2 R22.1 U10.4(SET) U11.4(SET)
N17244733: C17.1 R21.1 U9.6(OUTS) U9.7(OUTF)
N17247554: C18.1 L4.2 U9.1(~{SHDN}) U9.2(VIN)
N17261030: L2.1 L3.1 Q2.5(DRAIN) Q2.6(DRAIN) Q2.7(DRAIN) Q2.8(DRAIN)
N17448911: C25.2 C27.1 L7.2 U2.9(VPLL)
N17449258: C26.2 C28.1 L6.2 U2.4(VPHY)
N17522038: C39.1 U2.2(OSCI) Y1.1
N17522859: C38.1 U2.3(OSCO) Y1.3
N17564151: E8.1(A) R45.2 U1.M2(FSADJ)
N17564536: C40.1 E9.1(A) U1.M1(REFIO)
N17565124: R23.1 R40.1 R43.1 R47.1 R57.1 R61.2 U1.H1(IOUTP)
N17565323: R24.1 R25.1 R46.2 R48.2 R58.1 R60.1 U1.J1(IOUTN)
N17689883: J1.7(MOSI/SDA) R33.1 R37.1 U1.S3(SD0)
N17690837: J1.4(SCK/SCL) R34.1 R38.1 U1.S5(SCK)
N17691854: J1.5(MISO) R32.1 R36.1 U1.S4(SDI)
N17692337: J1.6(CS) R35.1 R39.1 U1.S2(~{CS})
N17692824: J1.14(GPIO) R31.1 R41.2 R42.2 U1.S1(~{PD})
N17881529: E10.1(A) U1.R4(TSTP)
N17882089: E11.1(A) U1.R3(TSTN)
N17956548: C41.2 R29.1 U1.A3(CKP)
N17957137: C42.2 R26.1 U1.A2(CKN)
N18764925: JP1.2 R41.1
N19784334: C44.1 C73.1 L9.1 Q1.5(DRAIN) Q1.6(DRAIN) Q1.7(DRAIN) Q1.8(DRAIN) R54.2 U12.1(OUT)
N19818447: C44.2 D2.1(C) R30.1 U12.6(VSS) U12.7(PAD)
N19831231: Q1.4(GATE) U12.2(GATE)
N19836691: D1.2(A) D2.2(A)
N20053871: C41.1 T1.6
N20056092: C42.1 T1.4
N20061787: C43.2 R26.2 R29.2
N20077692: C47.2 T1.2(IN)
N20111819: J5.1(CENTER) R58.2 R59.1
N20472726: C47.1 C65.1 L8.2
N20474575: C66.1 J4.1(CENTER) L8.1
N20533316: C72.2 R56.2 U10.5(VCTRL)
N20618804: C74.1 C76.1 C77.1 D3.2(ANODE) L10.2 R53.1 U8.4(VIN1) U8.13(VIN2) U8.14(EN/UV)
N20647783: C24.2 U8.16(TR/SS)
N20648359: R52.2 R53.2 U8.17(SYNC/MODE)
N20658013: C22.2 U8.2(INTVCC)
N20664979: D3.1(CATHODE) U8.19(PG)
N20669836: R49.2 U8.15(RT)
N20685909: C21.2 U8.3(BST)
N20686508: C21.1 L5.1 U8.8(SW) U8.9(SW) U8.21(SW) U8.22(SW)
N20699898: C20.2 R50.2 R51.1 U8.20(FB)
N20728336: C75.1 L9.2 L10.1
N20749077: J8.1(CENTER) R52.1
N20881057: Q2.4(GATE) R54.1
N20963045: C71.2 R55.2 U11.5(VCTRL)
N20982842: J6.1(CENTER) R44.2 R57.2
N21181218: R44.1 R61.1 R62.2 R63.1
N21185428: R27.2 R28.1 R59.2 R60.2

Not connected (* = marked no-connect by the designer): J1 1(VUNREG)* 9(EESDA)* 10(EEVCC)* 11(EESCL)* 12(EEGND)*; J9 6* 7* 8*; J10 1(XCVR_TXP7)* 2(XCVR_RXP7)* 3(XCVR_TXN7)* 4(XCVR_RXN7)* 5(XCVR_TXP6)* 6(XCVR_RXP6)* 7(XCVR_TXN6)* 8(XCVR_RXN6)* 9(XCVR_TXP5)* 10(XCVR_RXP5)* 11(XCVR_TXN5)* 12(XCVR_RXN5)* 13(XCVR_TXP4)* 14(XCVR_RXP4)* 15(XCVR_TXN4)* 16(XCVR_RXN4)* 17(XCVR_TXP3)* 18(XCVR_RXP3)* 19(XCVR_TXN3)* 20(XCVR_RXN3)* 21(XCVR_TXP2)* 22(XCVR_RXP2)* 23(XCVR_TXN2)* 24(XCVR_RXN2)* 25(XCVR_TXP1) 26(XCVR_RXP1)* 27(XCVR_TXN1)* 28(XCVR_RXN1)* 29(XCVR_TXP0)* 30(XCVR_RXPO)* 31(XCVR_TXN0)* 32(XCVR_RXN0)* 33(SDA) 34(SCL) 35(JTAG_TCK)* 36(JTAG_TMS)* 37(JTAG_TDO)* 38(JTAG_TDI)* 39(CLKOUT0)* 40(CLKIN0)* 45(3V3)* 46(12V)* 47(LVDS_TXP0) 48(LVDS_RXP0) 49(LVDS_TXN0) 50(LVDS_RXN0) 51(3V3)* 52(12V)* 54(LVDS_RXP1) 56(LVDS_RXN1) 57(3V3)* 58(12V)* 60(LVDS_RXP2) 62(LVDS_RXN2) 63(3V3)* 64(12V)* 66(LVDS_RXP3) 68(LVDS_RXN3) 69(3V3)* 70(12V)* 72(LVDS_RXP4) 74(LVDS_RXN4) 75(3V3)* 76(12V)* 78(LVDS_RXP5) 80(LVDS_RXN5) 81(3V3)* 82(12V)* 84(LVDS_RXP6) 86(LVDS_RXN6) 87(3V3)* 88(12V)* 90(LVDS_RXP7) 92(LVDS_RXN7) 93(3V3)* 94(12V)* 95(CLKOUT1P) 96(CLKIN1P) 97(CLKOUT1N) 98(CLKIN1N) 99(3V3)* 100(12V)* 102(LVDS_RXP8) 104(LVDS_RXN8) 105(3V3)* 106(12V)* 108(LVDS_RXP9) 110(LVDS_RXN9) 111(3V3)* 112(12V)* 114(LVDS_RXP10) 116(LVDS_RXN10) 117(3V3)* 118(12V)* 120(LVDS_RXP11) 122(LVDS_RXN11) 123(3V3)* 124(12V)* 126(LVDS_RXP12) 128(LVDS_RXN12) 129(3V3)* 130(12V)* 132(LVDS_RXP13) 134(LVDS_RXN13) 135(3V3)* 136(12V)* 138(LVDS_RXP14) 140(LVDS_RXN14) 141(3V3)* 142(12V)* 144(LVDS_RXP15) 146(LVDS_RXN15) 147(3V3)* 148(12V)* 150(LVDS_RXP16)* 152(LVDS_RXN16)* 153(3V3)* 154(12V)* 155(CLKOUT2P)* 157(CLKOUT2N)* 159(3V3)* 160(12V)*; J11 1(XCVR_TXP7)* 2(XCVR_RXP7)* 3(XCVR_TXN7)* 4(XCVR_RXN7)* 5(XCVR_TXP6)* 6(XCVR_RXP6)* 7(XCVR_TXN6)* 8(XCVR_RXN6)* 9(XCVR_TXP5)* 10(XCVR_RXP5)* 11(XCVR_TXN5)* 12(XCVR_RXN5)* 13(XCVR_TXP4)* 14(XCVR_RXP4)* 15(XCVR_TXN4)* 16(XCVR_RXN4)* 17(XCVR_TXP3)* 18(XCVR_RXP3)* 19(XCVR_TXN3)* 20(XCVR_RXN3)* 21(XCVR_TXP2)* 22(XCVR_RXP2)* 23(XCVR_TXN2)* 24(XCVR_RXN2)* 25(XCVR_TXP1) 26(XCVR_RXP1)* 27(XCVR_TXN1)* 28(XCVR_RXN1)* 29(XCVR_TXP0)* 30(XCVR_RXPO)* 31(XCVR_TXN0)* 32(XCVR_RXN0)* 33(SDA) 34(SCL) 35(JTAG_TCK)* 36(JTAG_TMS)* 37(JTAG_TDO)* 38(JTAG_TDI)* 39(CLKOUT0)* 40(CLKIN0)* 43(D2) 44(D3) 45(3V3)* 46(12V)* 51(3V3)* 52(12V)* 57(3V3)* 58(12V)* 63(3V3)* 64(12V)* 69(3V3)* 70(12V)* 75(3V3)* 76(12V)* 81(3V3)* 82(12V)* 86(LVDS_RXN6) 87(3V3)* 88(12V)* 93(3V3)* 94(12V)* 99(3V3)* 100(12V)* 105(3V3)* 106(12V)* 111(3V3)* 112(12V)* 117(3V3)* 118(12V)* 123(3V3)* 124(12V)* 129(3V3)* 130(12V)* 135(3V3)* 136(12V)* 141(3V3)* 142(12V)* 147(3V3)* 148(12V)* 149(LVDS_TXP16)* 151(LVDS_TXN16)* 153(3V3)* 154(12V)* 159(3V3)* 160(12V)*; U4 7(NC)*; U12 5(~{SHDN})*

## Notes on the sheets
sheet 1
- 01/30/2014
- PD
- RUN
- SHDN
- DC590
- (TO PAGE 4)
- TO PAGE 4
- DIGITAL INPUTS [DA0..DA15] AND [DB0..DB15] FROM PAGE 4
- FSADJ
- REFIO
- IOUTPB
- U1*
- (FROM PAGE 4)
- IOUTNB
- (T0 PAGE 4)
- TRIG N
- TSTP
- TSTN
- NOTES:
- (T0 PAGE 4)
- 1. ALL RESISTORS ARE SIZE 0402, U.O.N.
- 2. REFER TO PAGE 4 FOR LTC2000 POWER CONNECTIONS.
- *
- ASSEMBLY TABLE
- TRIG P
- ASSY
- U1
- -A
- LTC2000IY-16
- -B
- LTC2000IY-14
- -C
- LTC2000IY-11
- CK
- -D
- LTC2000AIY-16
- -E
- LTC2000AIY-14
- -F
- LTC2000AIY-11
- LTC2000 HIGH SPEED DAC
- LTC2000-X FAMILY
- DEMO CIRCUIT 2085A
- 01/30/2014
sheet 2
- SVDD3V0
- AVDD1V8
- GND
- AVDD3V3
- +5V
- DVDD1V8
- DVDD3V3
- VP1
- POWER
- FAULT
- SYNC
- 2.2V
- LTC2000 HIGH SPEED DAC
- LTC2000-X FAMILY
- DEMO CIRCUIT 2085A
- 01/30/2014
- LTC2000 HIGH SPEED DAC
- LTC2000
- DEMO CIRCUIT 2085A
- 04/08/2013
sheet 3
- USB
- SCK_IF
- SDI_IF
- SDO_IF
- CS_IF
- JTAG
- JTAG
- SPI
- LTC2000 HIGH SPEED DAC
- LTC2000-X FAMILY
- DEMO CIRCUIT 2085A
- 01/30/2014
sheet 4
- HSMC CONNECTORS - MEZZANINE SIDE
- NET CONNECTIONS FOR LTC2000 POWER PINS TO PCB POWER NETS
- U1
- LTC2000  POWER CONNECTIONS
- LTC2000  POWER BYPASS CAPACITORS
- LTC2000 HIGH SPEED DAC
- LTC2000-X FAMILY
- DEMO CIRCUIT 2085A
- 01/30/2014
